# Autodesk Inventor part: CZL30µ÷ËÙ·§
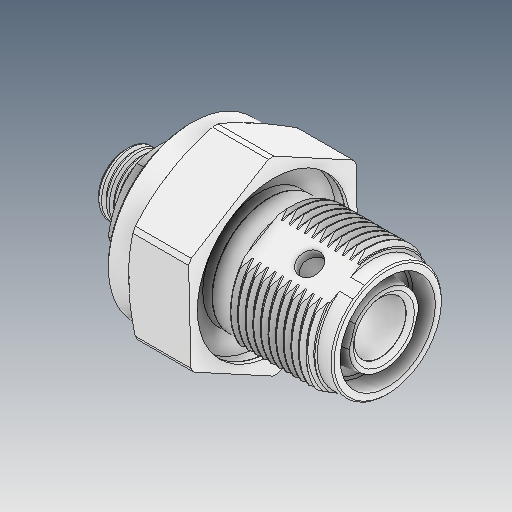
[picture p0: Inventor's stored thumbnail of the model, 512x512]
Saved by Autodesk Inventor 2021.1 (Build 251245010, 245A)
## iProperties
Created: 2021-05
Part Number: CZL30µ÷ËÙ·§
Material: Ogólny
Document SubType Name: Modeling
Designer: user
Density: 1 g/cm^3
Appearance: Domyślna
Author: user
Revision Number: ÈÎºÎ
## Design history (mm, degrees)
feature "ÊäÈë2"
feature "ÊäÈë4"
feature "ÊäÈë5"
node "Bryła1"
node "Bryła2"
node "Bryła3"
